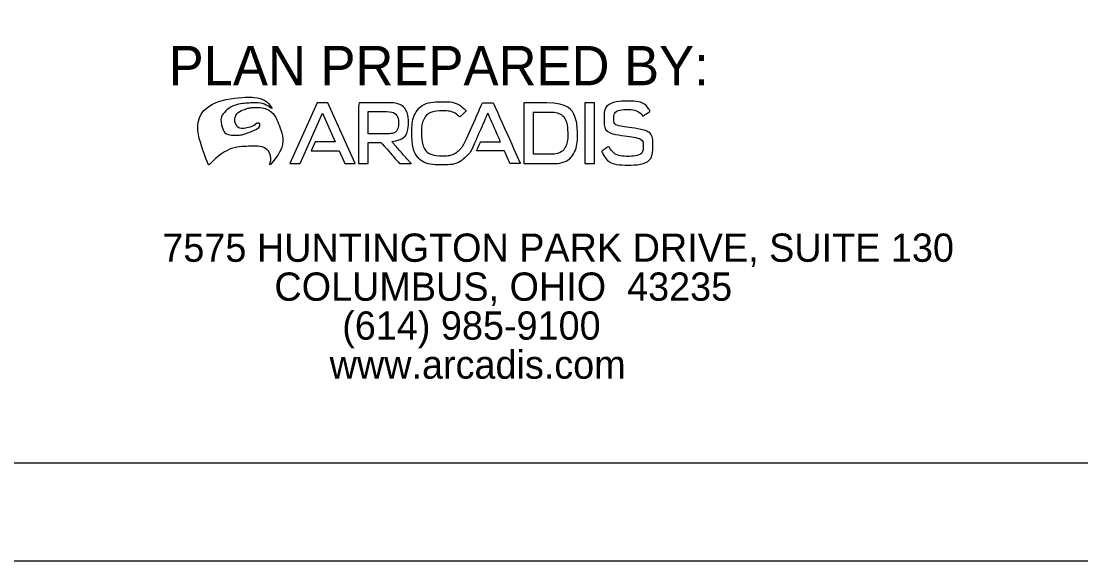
# Model space of a CAD drawing. Extents: x 39.5 to 73.5, y 15.6 to 37.6.
# Drawn here: x 42.4 to 47.83, y 15.6 to 18.37 of the extents above; entities that cross this region are included whole.
import ezdxf

# ---------------------------------------------------------------- set-up
doc = ezdxf.new("R2010")
doc.units = 0
for name, color, linetype in [('GM_X_City_Street', 7, 'Continuous'), ('GM_X_Hydro_Text', 7, 'Continuous'), ('GM_X_Interstate_Route', 7, 'Continuous'), ('GM_X_Major_River_Text', 7, 'Continuous')]:
    doc.layers.add(name, color=color, linetype=linetype)

msp = doc.modelspace()

# ---------------------------------------------------------------- linework, layer by layer
at = {"layer": 'GM_X_City_Street'}
msp.add_lwpolyline([(41.5012, 37.1011), (73.0012, 37.1011), (73.0012, 16.1011), (41.5012, 16.1011)], close=True, dxfattribs=at)
at = {"layer": 'GM_X_Hydro_Text'}
msp.add_lwpolyline([(39.5012, 15.6011), (73.5012, 15.6011), (73.5012, 37.6011), (39.5012, 37.6011)], close=True, dxfattribs=at)
at = {"layer": 'GM_X_Major_River_Text'}
for p, q in [((43.9148, 17.9506), (43.7746, 17.6382)), ((43.9692, 17.9506), (43.9148, 17.9506)), ((44.1093, 17.6382), (43.9692, 17.9506)), ((45.3375, 17.9506), (45.2879, 17.9506)), ((45.2879, 17.9506), (45.2879, 17.6382)), ((45.3375, 17.6382), (45.3375, 17.9506)), ((43.8278, 17.6382), (43.942, 17.898)), ((43.942, 17.898), (44.0073, 17.7494)), ((43.904, 17.7494), (43.884, 17.7038)), ((44.0073, 17.7494), (43.904, 17.7494)), ((43.884, 17.7038), (44.0273, 17.7038)), ((44.0273, 17.7038), (44.0562, 17.6382)), ((43.7746, 17.6382), (43.8278, 17.6382)), ((44.0562, 17.6382), (44.1093, 17.6382)), ((45.2879, 17.6382), (45.3375, 17.6382)), ((44.58, 17.2865), (44.58, 17.2865))]:
    msp.add_line(p, q, dxfattribs=at)
for points, degree in [([(43.5454, 17.9792), (43.2381, 17.9656), (43.3559, 17.6283), (43.3559, 17.6283), (43.3828, 17.6574), (43.469, 17.7268), (43.59, 17.7273), (43.5901, 17.7273), (43.5903, 17.7273), (43.5904, 17.7273), (43.6487, 17.7273), (43.683, 17.6777), (43.6698, 17.6284), (43.6698, 17.6284), (43.7606, 17.7348), (43.7101, 17.856), (43.6933, 17.8964), (43.6481, 17.9264), (43.5951, 17.9264), (43.5771, 17.9264), (43.5583, 17.923), (43.5394, 17.9153), (43.4951, 17.8974), (43.4891, 17.8573), (43.4982, 17.8388), (43.5048, 17.8252), (43.518, 17.8185), (43.5322, 17.8185), (43.5346, 17.8185), (43.537, 17.8186), (43.5394, 17.819), (43.5839, 17.826), (43.6021, 17.8466), (43.6124, 17.8466), (43.6138, 17.8466), (43.6151, 17.8462), (43.6163, 17.8453), (43.6229, 17.8402), (43.6166, 17.8193), (43.5596, 17.7963), (43.5458, 17.7908), (43.5205, 17.7843), (43.4956, 17.7843), (43.4665, 17.7843), (43.4379, 17.7931), (43.4283, 17.8224), (43.4104, 17.8769), (43.4745, 17.9422), (43.5708, 17.9497), (43.5757, 17.9501), (43.5823, 17.9504), (43.587, 17.9504), (43.6359, 17.9504), (43.6711, 17.9283), (43.6884, 17.9137), (43.6685, 17.9472), (43.6265, 17.9779), (43.5587, 17.9791), (43.5587, 17.9791), (43.5531, 17.9793), (43.5454, 17.9792), (43.5454, 17.9792), (43.5454, 17.9792), (43.5454, 17.9792)], 3), ([(44.2974, 17.7511), (44.359, 17.7601), (44.3822, 17.8038), (44.3822, 17.8484), (44.3822, 17.9011), (44.3443, 17.9507), (44.272, 17.9507), (44.2234, 17.9507), (44.1752, 17.9506), (44.1265, 17.9506), (44.1265, 17.9506), (44.1265, 17.6382), (44.1265, 17.6382), (44.1265, 17.6382), (44.1765, 17.6382), (44.1765, 17.6382), (44.1765, 17.6382), (44.1765, 17.7462), (44.1765, 17.7462), (44.1765, 17.7462), (44.2425, 17.7462), (44.2425, 17.7462), (44.2425, 17.7462), (44.3376, 17.6382), (44.3376, 17.6382), (44.3376, 17.6382), (44.3962, 17.6382), (44.3962, 17.6382)], 3), ([(44.8173, 17.9507), (44.8173, 17.9507), (44.7629, 17.9507), (44.7629, 17.9507), (44.7629, 17.9507), (44.672, 17.748), (44.672, 17.748), (44.672, 17.748), (44.672, 17.748), (44.672, 17.748), (44.6622, 17.7287), (44.6515, 17.7165), (44.6477, 17.7125), (44.6259, 17.6908), (44.5939, 17.6789), (44.5651, 17.6789), (44.4843, 17.6789), (44.4504, 17.7355), (44.4499, 17.7927), (44.4495, 17.8502), (44.4856, 17.9087), (44.5651, 17.9087), (44.5941, 17.9087), (44.6235, 17.8984), (44.6458, 17.8766), (44.6458, 17.8766), (44.6793, 17.9087), (44.6793, 17.9087), (44.6476, 17.9404), (44.607, 17.956), (44.5651, 17.956), (44.4535, 17.956), (44.3999, 17.8743), (44.4004, 17.7922), (44.4008, 17.7101), (44.4517, 17.632), (44.5651, 17.632), (44.6088, 17.632), (44.6503, 17.6467), (44.6824, 17.6784), (44.6824, 17.6784), (44.7023, 17.6983), (44.7152, 17.7276), (44.7152, 17.7276), (44.7191, 17.7365), (44.7191, 17.7365), (44.7191, 17.7365), (44.7282, 17.7573), (44.7282, 17.7573), (44.7282, 17.7573), (44.7282, 17.7573), (44.7282, 17.7573), (44.7282, 17.7573), (44.7901, 17.898), (44.7901, 17.898), (44.7901, 17.898), (44.8554, 17.7494), (44.8554, 17.7494), (44.8554, 17.7494), (44.7521, 17.7494), (44.7521, 17.7494), (44.7521, 17.7494), (44.7321, 17.7038), (44.7321, 17.7038), (44.7321, 17.7038), (44.8754, 17.7038), (44.8754, 17.7038), (44.8754, 17.7038), (44.9043, 17.6382), (44.9043, 17.6382), (44.9043, 17.6382), (44.9574, 17.6382), (44.9574, 17.6382), (44.9574, 17.6382), (44.8173, 17.9507), (44.8173, 17.9507), (44.8173, 17.9507), (44.8173, 17.9507), (44.8173, 17.9507)], 3), ([(45.093, 17.9506), (45.093, 17.9506), (44.9747, 17.9506), (44.9747, 17.9506)], 2), ([(44.9747, 17.9506), (44.9747, 17.9506), (44.9747, 17.6382), (44.9747, 17.6382), (44.9747, 17.6382), (45.093, 17.6382), (45.093, 17.6382), (45.2023, 17.6382), (45.2514, 17.7181), (45.2497, 17.7971), (45.2483, 17.8743), (45.1997, 17.9506), (45.093, 17.9506)], 3), ([(45.5854, 17.8815), (45.5707, 17.9029), (45.5408, 17.9158), (45.5082, 17.9163), (45.4663, 17.9163), (45.4359, 17.8989), (45.4359, 17.869), (45.4359, 17.8386), (45.4707, 17.8302), (45.5118, 17.8243), (45.5761, 17.8154), (45.6372, 17.7976), (45.6372, 17.7275), (45.6368, 17.6574), (45.573, 17.6311), (45.5078, 17.6311), (45.448, 17.6311), (45.402, 17.6494), (45.3735, 17.7021), (45.3735, 17.7021), (45.411, 17.7271), (45.411, 17.7271), (45.4333, 17.6891), (45.4721, 17.6757), (45.5082, 17.6757), (45.5457, 17.6757), (45.5872, 17.6882), (45.5872, 17.7275), (45.5872, 17.7614), (45.5511, 17.773), (45.5073, 17.7788), (45.4453, 17.7873), (45.3864, 17.8029), (45.3864, 17.8699), (45.386, 17.9346), (45.4507, 17.9596), (45.5069, 17.9596), (45.552, 17.9596), (45.5971, 17.9489), (45.6234, 17.9069), (45.6234, 17.9069), (45.5854, 17.8815), (45.5854, 17.8815), (45.5854, 17.8815), (45.5854, 17.8815), (45.5854, 17.8815)], 3), ([(44.1765, 17.9051), (44.1765, 17.9051), (44.272, 17.9051), (44.272, 17.9051)], 2), ([(44.272, 17.9051), (44.3131, 17.9051), (44.3314, 17.8757), (44.3314, 17.8476), (44.3314, 17.8181), (44.3131, 17.7918), (44.2716, 17.7918), (44.2716, 17.7918), (44.1765, 17.7918), (44.1765, 17.7918), (44.1765, 17.7918), (44.1765, 17.9051), (44.1765, 17.9051)], 3), ([(45.0243, 17.6864), (45.0243, 17.6864), (45.0243, 17.9029), (45.0243, 17.9029)], 2), ([(45.0243, 17.9029), (45.0243, 17.9029), (45.093, 17.9029), (45.093, 17.9029), (45.1666, 17.9029), (45.1988, 17.8502), (45.2001, 17.7976), (45.2015, 17.7427), (45.1693, 17.6864), (45.093, 17.6864), (45.093, 17.6864), (45.0243, 17.6864), (45.0243, 17.6864)], 3), ([(44.3962, 17.6382), (44.3962, 17.6382), (44.2974, 17.7511), (44.2974, 17.7511)], 2)]:
    msp.add_open_spline(points, degree=degree, dxfattribs=at)

# ---------------------------------------------------------------- texts
at = {"layer": 'GM_X_Interstate_Route'}
msp.add_text('PLAN PREPARED BY:', height=0.2016, dxfattribs=at).set_placement((43.1521, 18.0403))
at = {"layer": 'GM_X_Major_River_Text'}
for s, p in [('7575 HUNTINGTON PARK DRIVE, SUITE 130', (43.1197, 17.1348)), ('COLUMBUS, OHIO  43235', (43.6948, 16.935)), ('(614) 985-9100', (44.0429, 16.7352)), ('www.arcadis.com', (43.9782, 16.5353))]:
    msp.add_text(s, height=0.145, dxfattribs=at).set_placement(p)

doc.saveas('drawing.dxf')
